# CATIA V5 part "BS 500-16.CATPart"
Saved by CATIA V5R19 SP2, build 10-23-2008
Part number: BS 500-16
Bounding box of the stored display mesh (mm): x -18.951 to 18.951, y -18.952 to 18.952, z 0 to 62
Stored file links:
  C:\Users\Bora\Desktop\3D Katı model\BS serisi\BS 500\BS 500-16.CATPart
  C:\Program Files\Dassault Systemes\B19\intel_a\reffiles\standard\MetricThickPitch.txt
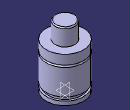
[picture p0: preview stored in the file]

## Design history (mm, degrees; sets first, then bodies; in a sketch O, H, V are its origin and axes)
Body1 (main body)
  Sketch1 on yz-plane, origin (0, 0, 0), H (0, 1, 0), V (0, 0, 1)
    point P1 (10, 61)
    point P3 (10, 61)
    point P5 (19, 35.5)
    point P6 (19, 33.5)
    point P9 (19, 35.5)
    point P14 (19, 33.5)
    line L1 (10, 61) -> (10, 45)
    arc A1 centre (9, 61) radius 1 from (10, 61) to (9, 62) ccw
    arc A2 centre (19, 34.5) radius 1 from (19, 35.5) to (19, 33.5) ccw
    line L2 (19, 0) -> (19, 4)
    line L3 (19, 35.5) -> (19, 45)
    line L4 (17, 7.5) -> (17, 4)
    line L5 (19, 7.5) -> (19, 33.5)
    line L6 (9, 62) -> (0, 62)
    point P15 (0, 62)
    line L7 (10, 45) -> (19, 45)
    line L8 (0, 0) -> (19, 0)
    line L9 (17, 7.5) -> (19, 7.5)
    line L10 (17, 4) -> (19, 4)
    coincidence: P15 V, P1 P3, P5 P9, P6 P14
    tangency: L6 A1
    horizontal: L7 H, L8 H, L9 H, L10 H
  Shaft1: profile Sketch1, axis Sketch1.V, angle 360
  Sketch2 on face of Shaft1 from Sketch1.L8, origin (0, 0, 0), H (1, 0, 0), V (0, -1, 0)
    point P1 (0, 0)
  Hole1: placed by Sketch2, at (0, 0, 0) direction (0, 0, 1), diameter 6.647, depth 4, threaded "M8", thread diameter 8, thread depth 4, pitch 1.25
